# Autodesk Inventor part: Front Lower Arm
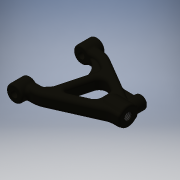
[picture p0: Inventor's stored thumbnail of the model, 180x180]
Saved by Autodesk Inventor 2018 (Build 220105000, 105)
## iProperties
Shininess: 41.0
Compacted: True
Length Units: 11272
Angle Units: 11279
Time Units: 11290
Mass Units: 11286
Length Display Precision: 3
Angle Display Precision: 2
Company: Autodesk
Created: 2001-02
Part Number: Front Lower Arm
Document SubType Name: Modeling
Designer: Autodesk, Inc.
Project: Inventor Samples
Density: 1.28 g/cm^3
Mass: 4.8425 g
Surface Area: 27.2674 cm^2
Volume: 3.7832 cm^3
Material: Stiffzel
Appearance: Stiffzel
Density: 0.0
Volumn: 0.0
Area: 0.0
PropertySet Name: Model Information
Control State: 0
Master: False
Checked Out: False
Author: Autodesk, Inc.
Revision Number: A
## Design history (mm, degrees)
sketch "Sketch1"
  geometry: C1 r 4.001 at (-10.325, -2.008)
  constraints: 1 centre point
  dimensions: "d0" = 8.001 diameter of C1
extrude "Extrusion1" new body sketch "Sketch1" distance "d1" = 8.001 (= d0); taper "d2" = 0 deg
workaxis "Work Axis2"
workplane "Work Plane1"
sketch "Sketch2"
  geometry: C1 r 4.001 at (0, 0) reference
extrude "Extrusion2" join sketch "Sketch2" distance "d4" = 8.001 (= d1); taper "d5" = 0 deg
workplane "Work Plane2"
sketch "Sketch3"
  geometry: L1 (-35.418, -10.846)-(5.38, -10.846); L2 (-38.1, -6.083)-(-25.4, -6.083); L3 (-25.4, -6.083)-(-25.4, -15.608); L4 (-25.4, -15.608)-(-38.1, -15.608); L5 (-38.1, -15.608)-(-38.1, -6.083); L6 (-4.001, 8.001)-(4.001, 8.001) reference; L7 (0, -41.681)-(0, 16.281) reference; L8 (-4.001, 0)-(4.001, 0) reference; L9 (4.001, -25.4)-(-4.001, -25.4) reference; L10 (4.001, -33.401)-(-4.001, -33.401) reference; L11 (0, 0)-(0, 5.08); L12 (0, 5.08)-(-8.001, 5.08); L13 (0, 0)-(-8.001, 0); L14 (0, -25.4)-(-8.001, -25.4); L15 (0, -30.48)-(-8.001, -30.48); L16 (-8.001, 5.08)-(-33.338, -6.083); L17 (-33.338, -15.608)-(-8.001, -30.48); L18 (-8.001, 0)-(-25.4, -7.666); L19 (-25.4, -15.187)-(-8.001, -25.4); L20 (0, -25.4)-(0, -30.48); L21 (-8.001, 0)-(-13.882, -21.948); L22 (-12.473, -1.971)-(-17.29, -19.947)
  constraints: 34 end point, 12 parallel, 9 point on line, 3 perpendicular, 2 midpoint, 1 collinear, 1 horizontal, 1 vertical alignment
  dimensions: "d10" = 18.8468 distance between parallel lines of L6 L1; "d11" = 38.1 distance between parallel lines of L7 L5; "d12" = 9.525 distance of L4.end L2.start; "d13" = 4.7625 distance between parallel lines of L2 L1 (= 0.5 x d12); "d14" = 12.7 distance of L3.end L4.end; "d15" = 5.08 distance between parallel lines of L15 L14; "d16" = 5.08 distance between parallel lines of L13 L12 (= d15); "d17" = 8.001 distance of L11.end L12.end; "d18" = 4.7625 distance from line of L5 L17.start; "d26" = 3.81 distance between parallel lines of L21 L22; "d27" = 105 deg angle of L13 L21
extrude "Extrusion3" join sketch "Sketch3" stored distance "d20" = 6.35; taper "d21" = 0 deg
fillet "Fillet1" dims "d22" = 8.001
fillet "Fillet3" dims "d24" = 12.7
fillet "Fillet5" dims "d28" = 1.5875
fillet "Fillet6" dims "d29" = 1.5875
fillet "Fillet7" dims "d30" = 8.001
fillet "Fillet8" dims "d31" = 3.175, "d32" = 1.5875
fillet "Fillet9" dims "d33" = 1.5875
fillet "Fillet10" dims "d34" = 0.8128
fillet "Fillet11" dims "d35" = 1.5875
sketch "Sketch4"
  geometry: L1 (-8.632, -2.353)-(-13.256, -19.612) reference; L2 (-2.764, -25.4)-(-5.826, -25.4) reference; A1 r 12.413 centre (1.046, -14.195) between (-10.944, -10.983) and (-4.295, -25.4)
  constraints: 2 midpoint, 2 point on circle, 1 centre point, 1 tangent
feature "Rib1" sketch "Sketch4" dims "d37" = 2.54, "d38" = 2.54
fillet "Fillet13" dims "d39" = 0.8128
fillet "Fillet14" dims "d40" = 0.8128
sketch "Sketch5"
  geometry: L1 (-4.01, -0.325)-(-9.479, -7.009)
  constraints: 2 end point
feature "Rib2" sketch "Sketch5" dims "d41" = 2.54, "d42" = 2.54
fillet "Fillet15" dims "d43" = 0.8128
fillet "Fillet16" dims "d44" = 0.8128
sketch "Sketch6"
  geometry: L1 (-1.587, 0)-(-7.937, 3.175); C1 r 4.763 at (-4.762, 1.587); A1 r 1.587 centre (-1.587, 0) between (-1.587, -1.587) and (0, 0) reference; A2 r 1.587 centre (-7.937, 3.175) between (-7.937, 4.762) and (-9.525, 3.175) reference
  constraints: 2 end point, 1 centre point, 1 midpoint
  dimensions: "d45" = 9.525 diameter of C1
extrude "Extrusion4" join sketch "Sketch6" distance "d46" = 9.8425; taper "d47" = 0 deg
fillet "Fillet17" dims "d48" = 0.8128
fillet "Fillet18" dims "d49" = 0.8128
fillet "Fillet19" dims "d50" = 0.8128
workplane "Work Plane3"
sketch "Sketch7"
  geometry: C1 r 3.188 at (0, 0) reference; C2 r 1.587 at (0, 0)
  constraints: 1 centre point, 1 coincident
  dimensions: "d52" = 3.175 diameter of C2
extrude "Extrusion5" cut sketch "Sketch7" extent not by distance; stored distance "d53" = 8.001; taper "d54" = 0 deg
sketch "Sketch8"
  geometry: L1 (-11.008, 1.587)-(47.933, 1.587) reference; L2 (-2.588, 3.175)-(-2.588, 0) reference; C1 r 3.175 at (0.841, 1.587)
  constraints: 1 centre point, 1 point on line
  dimensions: "d55" = 6.35 diameter of C1; "d56" = 3.429 distance from line of L2 C1.centre
extrude "Extrusion6" join sketch "Sketch8" stored distance "d57" = 8.001; taper "d58" = 0 deg
fillet "Fillet20" dims "d59" = 0.381
sketch "Sketch9"
  geometry: L1 (0, 0)-(8.496, 0); C1 r 3.175 at (0, 0) reference
  constraints: 2 end point, 1 horizontal
feature "Rib3" sketch "Sketch9" dims "d60" = 2.54, "d61" = 2.54
fillet "Fillet22" dims "d63" = 0.3556
fillet "Fillet23" dims "d64" = 0.8128
fillet "Fillet24" dims "d65" = 0.8128
sketch "Sketch10"
  geometry: A1 r 2.362 centre (0.841, 1.587) between (2.938, 2.675) and (2.938, 0.5) reference
hole "Hole1" sketch "Sketch10" at (0.841, 1.587) diameter "d66" = 2.159; stored, may be unused: countersink angle "d70" = 60 deg, drill point angle "d72" = 118 deg; dims "d67" = 12.7, "d68" = 9.525, "d69" = 6.35, "d71" = 6.35
fillet "Fillet25" dims "d73" = 0.3556
fillet "Fillet26" dims "d74" = 0.3556
sketch "Sketch11"
  geometry: A1 r 3.95 centre (0, 0) between (3.395, 2.019) and (2.967, -2.607); A2 r 3.95 centre (0, 0) between (2.879, 2.704) and (-2.879, 2.704) reference
  constraints: 2 concentric, 2 point on circle, 1 centre point
hole "Hole2" sketch "Sketch11" at (0, 0) diameter "d81" = 3.4036; stored, may be unused: drill point angle "d76" = 118 deg, countersink angle "d77" = 60 deg; dims "d75" = 12.7, "d78" = 6.35, "d79" = 9.525, "d80" = 9.525
chamfer "Chamfer1" distance "d82" = 0.381; stored, may be unused: second distance "d83" = 0.381, angle "d84" = 45 deg
body "Solid1"
other parameters: "d3" = 25.4, "d8" = 0, "d9" = 0, "d51" = 5.08
